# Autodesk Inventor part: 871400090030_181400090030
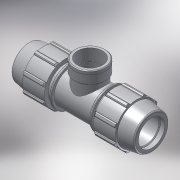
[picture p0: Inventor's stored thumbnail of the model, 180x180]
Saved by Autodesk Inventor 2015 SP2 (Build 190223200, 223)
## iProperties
Created: 2017-02
Part Number: 871400090030_181400090030
Material: PVC-Piping
Description: PLASSON TEE WITH THREADED FEMALE OFFTAKE 90-3."-90
Document SubType Name: Modeling
Designer: KIM
Mass: 92.6774 g
Surface Area: 199.44 cm^2
Volume: 66.1981 cm^3
Density: 1.4 g/cm^3
Appearance: Smooth - White
Author: KIM
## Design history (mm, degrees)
derived "87140.ipt"
feature "Solid1::87140.ipt"
feature "Solid2::87140.ipt"
tag "TaggingFeature1"
body "Solid1"
other parameters: "d4" = 17.41667, "d5" = 50.16, "d7" = 152, "d11" = 6.96667, "d13" = 120 deg, "d14" = 117, "d15" = 10 deg, "d16" = 132.24, "d18" = 4.5, "d19" = 35 deg, "d20" = 17.5 deg, "d21" = 141.36, "d23" = 0, "d25" = 360 deg, "d27" = 3.04, "d33" = 1.8, "d42" = 75.24, "d43" = 4.56, "d46" = 2.7, "d68" = 12.54, "d72" = 116, "d76" = 84.926, "d80" = 2.54778, "d91" = 114, "d93" = 164, "d95" = 81, "d112" = 41, "d115" = 106.1575, "d116" = 135 deg, "d117" = 97.6649, "d118" = 418, "d119" = 81, "d121" = 0, "d122" = 81, "d124" = 0, "d128" = 0, "d129" = 9, "d130" = 12.3, "d131" = 0.3, "d132" = 0.3, "d133" = 106.1575, "E_" = 152, "A_" = 116, "l_" = 164, "l_2" = 41, "Rp_" = 84.926, "H_" = 418
